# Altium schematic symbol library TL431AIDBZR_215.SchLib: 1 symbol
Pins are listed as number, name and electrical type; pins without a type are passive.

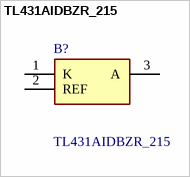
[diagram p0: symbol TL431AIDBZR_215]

## TL431AIDBZR_215
designator B?
Shunt Voltage Reference IC Adjustable 2.495V 36 VV +/-1% 100 mA TO-236AB; Manufacturer_Name: Nexperia; Manufacturer_Part_Number: TL431AIDBZR,215; Geometry.Height: 1.1mm
footprint SOT95P230X110-3N
pins: 1 K, 2 REF, 3 A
